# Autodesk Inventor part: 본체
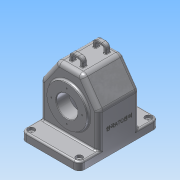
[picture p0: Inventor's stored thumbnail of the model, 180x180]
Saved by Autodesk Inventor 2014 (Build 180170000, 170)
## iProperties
Created: 2016-12
Part Number: 본체
Material: 알루미늄 6061
Document SubType Name: Modeling
Designer: net
Density: 2.71 g/cm^3
Appearance: 알루미늄 - 평지
Mass: 1067.07 g
Surface Area: 1138.25 cm^2
Volume: 393.753 cm^3
Author: net
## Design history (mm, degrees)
sketch "스케치1"
  geometry: L1 (-55, 75)-(55, 75); L2 (55, 75)-(55, -75); L3 (55, -75)-(-55, -75); L4 (-55, -75)-(-55, 75); L5 (-55, 75)-(55, -75); L6 (55, 75)-(-55, -75); 1 further point
  constraints: 12 end point, 2 midpoint, 2 parallel, 1 horizontal, 1 perpendicular
  dimensions: "d0" = 110 distance between parallel lines of L4 L2; "d1" = 150 distance between parallel lines of L1 L3
extrude "돌출1" new body sketch "스케치1" distance "d2" = 15; taper "d3" = 0 deg
sketch "스케치2"
  geometry: L1 (-55, 80)-(-55, 15); L2 (-55, 15)-(55, 15); L3 (55, 15)-(55, 80); L4 (55, 80)-(23.491, 125); L5 (23.491, 125)-(-23.491, 125); L6 (-23.491, 125)-(-55, 80); L7 (55, 15)-(-55, 15) reference; L8 (-55, 0)-(-55, 15) reference; L9 (-55, 0)-(55, 0) reference; 3 further points
  constraints: 12 end point, 2 collinear, 2 midpoint, 2 parallel, 2 vertical alignment, 1 perpendicular, 1 vertical
  dimensions: "d4" = 35 deg angle of L1 L6; "d5" = 35 deg angle of L3 L4; "d6" = 125 distance between parallel lines of L9 L5; "d7" = 80 distance from line of L9 L3.end
extrude "돌출2" join sketch "스케치2" stored distance "d8" = 77; taper "d9" = 0 deg
sketch "스케치3"
  geometry: C1 r 37.5 at (0, 65); 1 further point
  constraints: 1 centre point, 1 vertical alignment
  dimensions: "d10" = 75 diameter of C1; "d11" = 65 distance of point (0, 0) C1.centre
extrude "돌출3" join sketch "스케치3" distance "d12" = 5; taper "d13" = 0 deg
sketch "스케치4"
  geometry: C1 r 37.5 at (0, 65) reference; C2 r 31 at (0, 65); 1 further point
  constraints: 1 centre point, 1 coincident
  dimensions: "d14" = 62 diameter of C2
extrude "돌출4" join sketch "스케치4" distance "d15" = 10; taper "d16" = 0 deg
sketch "스케치5"
  geometry: L1 (-55, 15)-(-55, 80) reference; L2 (-55, 80)-(-23.491, 125) reference; L3 (-23.491, 125)-(23.491, 125) reference; L4 (23.491, 125)-(55, 80) reference; L5 (55, 80)-(55, 15) reference; L6 (50, 0)-(50, 78.424); L7 (50, 78.424)-(20.888, 120); L8 (20.888, 120)-(-20.888, 120); L9 (-20.888, 120)-(-50, 78.424); L10 (-50, 78.424)-(-50, 0); L11 (-55, 0)-(55, 0) reference; L12 (-50, 0)-(50, 0); 1 further point
  constraints: 12 end point, 2 equal length, 2 point on line, 1 collinear, 2 other
  dimensions: "d149" = 5 distance between parallel lines of L9 L2; "d150" = 5 distance between parallel lines of L10 L1
extrude "돌출5" cut sketch "스케치5" stored distance "d19" = 67; taper "d20" = 0 deg
node "작업 평면1"
sketch "스케치13"
  geometry: C1 r 31 at (0, 0) reference; C2 r 27 at (0, 0); 1 further point
  constraints: 1 centre point, 1 coincident
  dimensions: "d132" = 54 diameter of C2
extrude "돌출10" join sketch "스케치13" stored distance "d133" = 15; taper "d134" = 45 deg
hole "구멍1" diameter "d23" = 40; stored, may be unused: countersink angle "d27" = 90 deg, drill point angle "d29" = 118 deg; dims "d21" = 10, "d22" = 10, "d24" = 6, "d25" = 4, "d26" = 2, "d28" = 8
sketch "스케치6"
  geometry: C1 r 20 at (0, 0) reference; 2 further points
  constraints: 1 vertical alignment
  dimensions: "d30" = 29 distance of C1.centre point (0, 29)
hole "구멍2" sketch "스케치6" at (0, 29) diameter "d31" = 2.459; stored, may be unused: countersink angle "d35" = 90 deg, drill point angle "d37" = 118 deg; dims "d32" = 6, "d33" = 4, "d34" = 2, "d36" = 8
sketch "스케치7"
  geometry: C1 r 20 at (0, 0) reference; 2 further points
  constraints: 1 vertical alignment
  dimensions: "d41" = 26 distance of C1.centre point (0, 26)
hole "구멍3" sketch "스케치7" at (0, 26) diameter "d42" = 2.459; stored, may be unused: countersink angle "d46" = 90 deg, drill point angle "d48" = 118 deg; dims "d43" = 6, "d44" = 4, "d45" = 2, "d47" = 8
fillet "모깎기1" dims "d52" = 10
sketch "스케치8"
  geometry: L1 (-55, 65)-(-55, 38.5) reference; L2 (-55, 38.5)-(55, 38.5) reference; L3 (55, 38.5)-(55, 65) reference; L4 (45, 75)-(-45, 75) reference; C1 r 6 at (-45, 65); C2 r 6 at (45, 65); C3 r 6 at (45, -65); C4 r 6 at (-45, -65); A1 r 10 centre (-45, -65) between (-55, -65) and (-45, -75) reference; A2 r 10 centre (45, -65) between (45, -75) and (55, -65) reference; A3 r 10 centre (-45, 65) between (-45, 75) and (-55, 65) reference; A4 r 10 centre (45, 65) between (55, 65) and (45, 75) reference; 1 further point
  constraints: 4 centre point, 4 coincident, 3 equal radius
  dimensions: "d53" = 12 diameter of C4
extrude "돌출6" cut sketch "스케치8" distance "d54" = 5; taper "d55" = 0 deg
hole "구멍4" diameter "d58" = 5; stored, may be unused: countersink angle "d62" = 90 deg, drill point angle "d64" = 118 deg; dims "d56" = 10, "d57" = 10, "d59" = 6, "d60" = 4, "d61" = 2, "d63" = 8
hole "구멍5" diameter "d67" = 5; stored, may be unused: countersink angle "d71" = 90 deg, drill point angle "d73" = 118 deg; dims "d65" = 10, "d66" = 10, "d68" = 6, "d69" = 4, "d70" = 2, "d72" = 8
hole "구멍6" diameter "d76" = 5; stored, may be unused: countersink angle "d80" = 90 deg, drill point angle "d82" = 118 deg; dims "d74" = 10, "d75" = 10, "d77" = 6, "d78" = 4, "d79" = 2, "d81" = 8
hole "구멍7" diameter "d85" = 5; stored, may be unused: countersink angle "d89" = 90 deg, drill point angle "d91" = 118 deg; dims "d83" = 10, "d84" = 10, "d86" = 6, "d87" = 4, "d88" = 2, "d90" = 8
sketch "스케치9"
  geometry: L1 (35.991, 20.5)-(10.991, 20.5); L2 (10.991, 20.5)-(10.991, 12.5); L3 (10.991, 12.5)-(35.991, 12.5); L4 (35.991, 12.5)-(35.991, 20.5); L5 (35.991, 20.5)-(10.991, 12.5); L6 (10.991, 20.5)-(35.991, 12.5); L7 (10.991, 56.5)-(35.991, 56.5); L8 (35.991, 56.5)-(35.991, 64.5); L9 (35.991, 64.5)-(10.991, 64.5); L10 (10.991, 64.5)-(10.991, 56.5); L11 (10.991, 56.5)-(35.991, 64.5); L12 (35.991, 56.5)-(10.991, 64.5); 5 further points
  constraints: 24 end point, 6 midpoint, 4 parallel, 2 horizontal, 2 perpendicular, 2 vertical alignment, 1 collinear
  dimensions: "d92" = 25 distance between parallel lines of L4 L2; "d94" = 36 distance between parallel lines of L7 L1; "d95" = 52 distance between parallel lines of L9 L3; "d97" = 8 distance between parallel lines of L1 L3; "d99" = 18 distance from line of point (23.491, 38.5) L1
extrude "돌출7" join sketch "스케치9" distance "d100" = 15; taper "d101" = 0 deg
sketch "스케치10"
  geometry: L1 (25, 0)-(0, 0) reference; L2 (0, 15)-(25, 15) reference; L3 (5, 10)-(20, 10); L4 (20, 10)-(20, 0); L5 (20, 0)-(5, 0); L6 (5, 0)-(5, 10); 3 further points
  constraints: 8 end point, 2 midpoint, 2 parallel, 1 collinear, 1 horizontal, 1 perpendicular, 1 vertical alignment
  dimensions: "d102" = 15 distance between parallel lines of L4 L6; "d103" = 5 distance between parallel lines of L2 L3
extrude "돌출8" cut sketch "스케치10" stored distance "d104" = 15; taper "d105" = 0 deg
fillet "모깎기2" dims "d106" = 8
fillet "모깎기3" dims "d107" = 3
fillet "모깎기4" dims "d108" = 1
fillet "모깎기12" dims "d120" = 3
fillet "모깎기13" dims "d121" = 3
fillet "모깎기14" dims "d122" = 3
fillet "모깎기15" dims "d123" = 1
fillet "모깎기16" dims "d124" = 1
fillet "모깎기17" dims "d125" = 10
chamfer "모따기1" distance "d126" = 1; stored, may be unused: second distance "d127" = 2, angle "d128" = 45 deg
chamfer "모따기2" distance "d129" = 1; stored, may be unused: second distance "d130" = 2, angle "d131" = 45 deg
fillet "모깎기18" dims "d135" = 3
sketch "스케치14"
  geometry: L1 (140, 0)-(130, 0) reference; L2 (26.5, 15)-(26.5, 76.847) reference; 2 further points
  constraints: 1 other
  dimensions: "d137" = 45 distance from line of L1 point (65, 45); "d146" = 38.5 distance from line of L2 point (65, 45)
feature "엠보싱1" sketch "스케치14" dims "d4" = 35 deg, "d5" = 35 deg, "d6" = 125, "d7" = 80, "d138" = 0.5, "d139" = 0
fillet "모깎기22" dims "d143" = 10
fillet "모깎기23" dims "d144" = 8
fillet "모깎기24" dims "d145" = 3
node "솔리드1"
pattern_circular "원형 패턴1" dims angle "d39" = 360 deg
pattern_circular "원형 패턴2" dims angle "d50" = 360 deg
node "투영된 루프1"
other parameters: "d111" = -24
